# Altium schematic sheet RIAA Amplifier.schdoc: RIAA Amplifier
size A4; Organization: Altium Limited; Address1: L3, 12a Rodborough Rd; Address2: Frenchs Forest; Address3: NSW; Address4: Australia 2086; DocumentNumber: 1; SheetNumber: 1; SheetTotal: 1
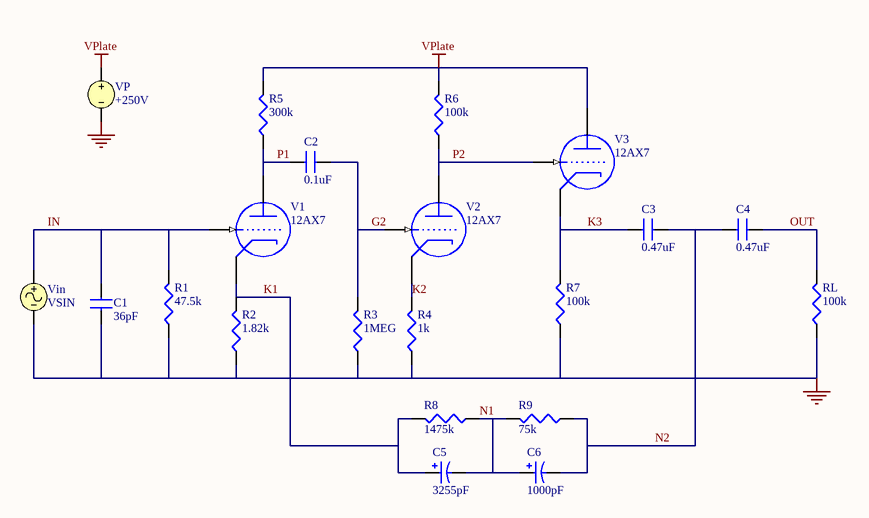
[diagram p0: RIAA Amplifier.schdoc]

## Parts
C1  36pF
C2  0.1uF
C3  0.47uF
C4  0.47uF
C5  3255pF
C6  1000pF
R1  47.5k
R2  1.82k
R3  1MEG
R4  1k
R5  300k
R6  100k
R7  100k
R8  1475k
R9  75k
RL  100k
V1  12AX7
V2  12AX7
V3  12AX7
Vin  VSIN
VP  +250V

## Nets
GND: C1.2 R1.2(BOT) R2.2(BOT) R3.2(BOT) R4.2(BOT) R7.2(BOT) RL.2(BOT) Vin.2 VP.2
VPlate: R5.1(TOP) R6.1(TOP) V3.1(P) VP.1
G2: C2.2 R3.1(TOP) V2.2(G)
IN: C1.1 R1.1(TOP) V1.2(G) Vin.1
K1: C5.1 R2.1(TOP) R8.1(TOP) V1.3(K)
K2: R4.1(TOP) V2.3(K)
K3: C3.1 R7.1(TOP) V3.3(K)
N1: C5.2 C6.1 R8.2(BOT) R9.1(TOP)
N2: C3.2 C4.1 C6.2 R9.2(BOT)
OUT: C4.2 RL.1(TOP)
P1: C2.1 R5.2(BOT) V1.1(P)
P2: R6.2(BOT) V2.1(P) V3.2(G)

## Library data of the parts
C1-C4 = CAP: Capacitor
C5 C6 = CAP2: Bi-Polar Capacitor
R1-R9 RL = RES: Resistor
V1-V3 = 12AX7: Triode
Vin = VSIN: Sinusoidal Voltage Source
VP = VSRC: Voltage Source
